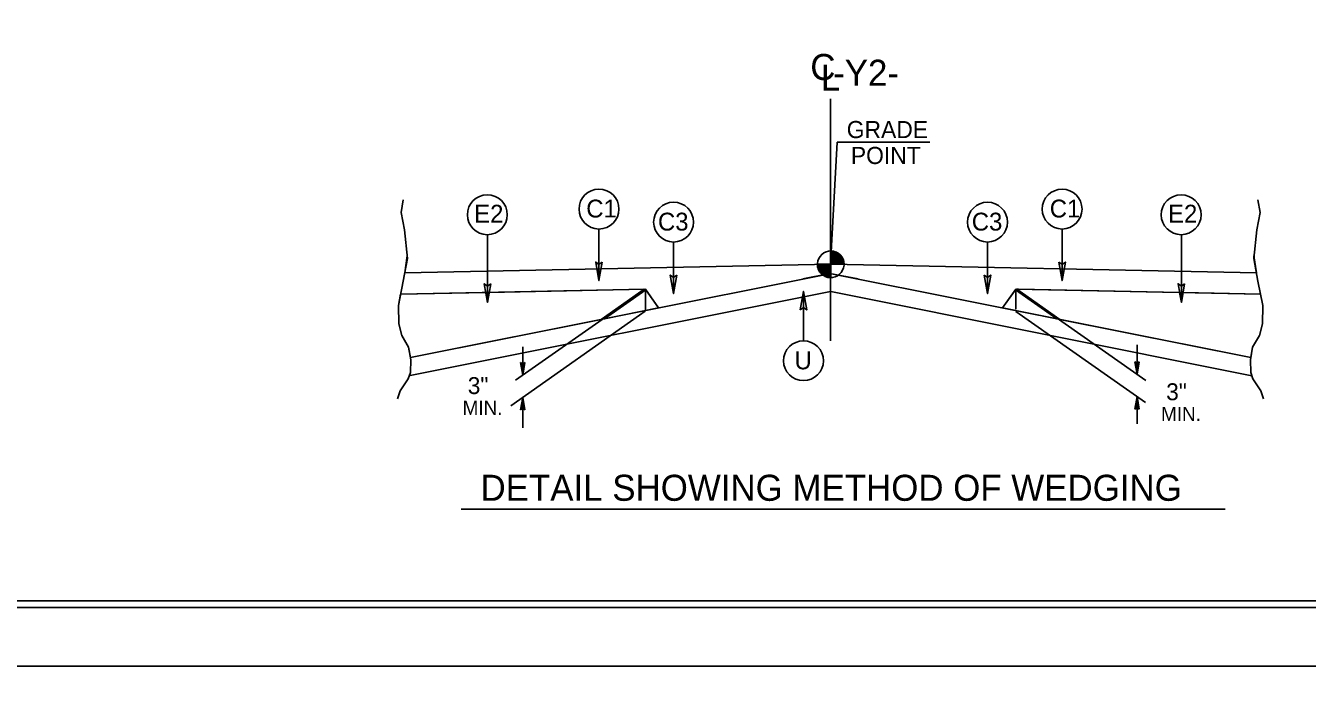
# Model space of a CAD drawing. Extents: x 1901718 to 1902220, y 193828 to 194187.
# Drawn here: x 1902024.12 to 1902073.27, y 194046.89 to 194072.58 of the extents above; entities that cross this region are included whole.
import ezdxf

# ---------------------------------------------------------------- set-up
doc = ezdxf.new("R2010")
doc.units = 0
for name, color, linetype in [('Old_Level_1', 7, 'Continuous'), ('Old_Level_11', 7, 'Continuous'), ('Old_Level_2', 7, 'Continuous'), ('Old_Level_20', 7, 'Continuous'), ('Old_Level_21', 7, 'Continuous'), ('Old_Level_3', 7, 'Continuous'), ('Sheet Border Standard 30in CELL', 7, 'Continuous'), ('Sheet Cutting Line CELL', 7, 'Continuous'), ('Sheet Plot Border Inside CELL', 7, 'Continuous'), ('Sheet Plot Border Outside CELL', 7, 'Continuous')]:
    doc.layers.add(name, color=color, linetype=linetype)

msp = doc.modelspace()

# ---------------------------------------------------------------- linework, layer by layer
at = {"layer": 'Old_Level_1'}
for p, q in [((1902054.991, 194063.427), (1902054.991, 194063.938)), ((1902054.479, 194063.427), (1902054.991, 194063.427)), ((1902054.988, 194062.916), (1902054.988, 194063.421)), ((1902054.991, 194063.427), (1902054.991, 194062.916)), ((1902055.503, 194063.427), (1902054.991, 194063.427)), ((1902054.991, 194062.916), (1902054.991, 194063.427)), ((1902047.882, 194062.471), (1902038.498, 194062.283)), ((1902054.978, 194062.385), (1902038.865, 194059.162)), ((1902047.882, 194062.471), (1902042.899, 194058.982)), ((1902048.392, 194061.754), (1902047.882, 194062.471)), ((1902047.882, 194062.471), (1902047.882, 194061.652)), ((1902054.991, 194062.385), (1902071.142, 194059.154)), ((1902061.578, 194061.755), (1902062.087, 194062.471)), ((1902062.087, 194062.471), (1902071.472, 194062.283)), ((1902062.087, 194062.471), (1902062.087, 194061.71)), ((1902062.088, 194062.471), (1902067.078, 194058.976)), ((1902047.878, 194061.627), (1902042.727, 194058.001)), ((1902047.882, 194061.653), (1902046.248, 194061.326)), ((1902061.577, 194061.755), (1902063.722, 194061.326)), ((1902062.087, 194061.611), (1902067.069, 194058.121)), ((1902046.248, 194061.326), (1902038.87, 194059.851)), ((1902043.18, 194060.262), (1902043.18, 194059.177)), ((1902066.74, 194060.342), (1902066.74, 194059.213)), ((1902043.18, 194059.177), (1902043.095, 194059.655)), ((1902043.18, 194059.593), (1902043.095, 194059.655)), ((1902043.18, 194059.177), (1902043.107, 194059.647)), ((1902043.12, 194059.637), (1902043.18, 194059.177)), ((1902043.18, 194059.177), (1902043.132, 194059.629)), ((1902043.144, 194059.62), (1902043.18, 194059.177)), ((1902043.18, 194059.177), (1902043.156, 194059.611)), ((1902043.168, 194059.602), (1902043.18, 194059.177)), ((1902043.18, 194059.177), (1902043.264, 194059.655)), ((1902043.264, 194059.655), (1902043.18, 194059.593)), ((1902043.252, 194059.647), (1902043.18, 194059.177)), ((1902043.18, 194059.177), (1902043.24, 194059.637)), ((1902043.228, 194059.629), (1902043.18, 194059.177)), ((1902043.18, 194059.177), (1902043.216, 194059.62)), ((1902043.204, 194059.611), (1902043.18, 194059.177)), ((1902043.18, 194059.177), (1902043.192, 194059.602)), ((1902043.18, 194059.593), (1902043.18, 194059.177)), ((1902066.74, 194059.213), (1902066.656, 194059.69)), ((1902066.74, 194059.629), (1902066.656, 194059.69)), ((1902066.74, 194059.213), (1902066.668, 194059.681)), ((1902066.679, 194059.673), (1902066.74, 194059.213)), ((1902066.74, 194059.213), (1902066.691, 194059.665)), ((1902066.703, 194059.655), (1902066.74, 194059.213)), ((1902066.74, 194059.213), (1902066.715, 194059.647)), ((1902066.727, 194059.637), (1902066.74, 194059.213)), ((1902066.74, 194059.213), (1902066.824, 194059.69)), ((1902066.824, 194059.69), (1902066.74, 194059.629)), ((1902066.811, 194059.681), (1902066.74, 194059.213)), ((1902066.74, 194059.213), (1902066.799, 194059.673)), ((1902066.787, 194059.665), (1902066.74, 194059.213)), ((1902066.74, 194059.213), (1902066.775, 194059.655)), ((1902066.764, 194059.647), (1902066.74, 194059.213)), ((1902066.74, 194059.213), (1902066.752, 194059.637)), ((1902066.74, 194059.629), (1902066.74, 194059.213)), ((1902043.18, 194058.319), (1902043.095, 194057.842)), ((1902043.108, 194057.851), (1902043.18, 194058.319)), ((1902043.18, 194058.319), (1902043.12, 194057.86)), ((1902043.132, 194057.868), (1902043.18, 194058.319)), ((1902043.18, 194058.319), (1902043.144, 194057.877)), ((1902043.156, 194057.886), (1902043.18, 194058.319)), ((1902043.18, 194058.319), (1902043.168, 194057.894)), ((1902043.18, 194058.319), (1902043.18, 194057.159)), ((1902043.18, 194058.319), (1902043.264, 194057.842)), ((1902043.18, 194057.904), (1902043.18, 194058.319)), ((1902043.192, 194057.894), (1902043.18, 194058.319)), ((1902043.18, 194058.319), (1902043.204, 194057.886)), ((1902043.216, 194057.877), (1902043.18, 194058.319)), ((1902043.18, 194058.319), (1902043.228, 194057.868)), ((1902043.24, 194057.86), (1902043.18, 194058.319)), ((1902043.18, 194058.319), (1902043.252, 194057.851)), ((1902066.74, 194058.352), (1902066.656, 194057.875)), ((1902066.656, 194057.875), (1902066.74, 194057.938)), ((1902066.668, 194057.884), (1902066.74, 194058.352)), ((1902066.74, 194058.352), (1902066.679, 194057.893)), ((1902066.691, 194057.902), (1902066.74, 194058.352)), ((1902066.74, 194058.352), (1902066.703, 194057.911)), ((1902066.715, 194057.92), (1902066.74, 194058.352)), ((1902066.74, 194058.352), (1902066.727, 194057.928)), ((1902066.74, 194058.352), (1902066.74, 194057.305)), ((1902066.74, 194058.352), (1902066.824, 194057.875)), ((1902066.74, 194057.938), (1902066.74, 194058.352)), ((1902066.752, 194057.928), (1902066.74, 194058.352)), ((1902066.74, 194058.352), (1902066.764, 194057.92)), ((1902066.775, 194057.911), (1902066.74, 194058.352)), ((1902066.74, 194058.352), (1902066.787, 194057.902)), ((1902066.799, 194057.893), (1902066.74, 194058.352)), ((1902066.74, 194058.352), (1902066.811, 194057.884)), ((1902066.74, 194057.938), (1902066.824, 194057.875)), ((1902043.095, 194057.842), (1902043.18, 194057.904)), ((1902043.18, 194057.904), (1902043.264, 194057.842))]:
    msp.add_line(p, q, dxfattribs=at)
for points in [[(1902038.598, 194065.896), (1902038.511, 194065.42), (1902038.641, 194064.744), (1902038.756, 194063.649), (1902038.598, 194062.785), (1902038.411, 194061.849), (1902038.425, 194061.143), (1902038.54, 194060.697), (1902038.8, 194060.25), (1902038.886, 194059.761), (1902038.872, 194059.271), (1902038.785, 194059.04), (1902038.483, 194058.579), (1902038.382, 194058.262)], [(1902071.371, 194065.896), (1902071.458, 194065.42), (1902071.328, 194064.744), (1902071.213, 194063.649), (1902071.371, 194062.785), (1902071.559, 194061.849), (1902071.544, 194061.143), (1902071.429, 194060.697), (1902071.17, 194060.25), (1902071.084, 194059.761), (1902071.098, 194059.271), (1902071.184, 194059.04), (1902071.486, 194058.579), (1902071.587, 194058.262)], [(1902054.996, 194063.938), (1902054.996, 194063.938), (1902054.996, 194063.427)], [(1902055.006, 194063.938), (1902055.006, 194063.427)], [(1902055.017, 194063.938), (1902055.017, 194063.427)], [(1902055.027, 194063.937), (1902055.027, 194063.427)], [(1902055.037, 194063.937), (1902055.037, 194063.427)], [(1902055.047, 194063.935), (1902055.047, 194063.427)], [(1902055.058, 194063.935), (1902055.058, 194063.427)], [(1902055.067, 194063.933), (1902055.067, 194063.427)], [(1902055.078, 194063.931), (1902055.078, 194063.427)], [(1902055.088, 194063.929), (1902055.088, 194063.427)], [(1902055.098, 194063.928), (1902055.098, 194063.427)], [(1902055.109, 194063.925), (1902055.109, 194063.427)], [(1902055.119, 194063.922), (1902055.119, 194063.427)], [(1902055.129, 194063.919), (1902055.129, 194063.427)], [(1902055.139, 194063.916), (1902055.139, 194063.427)], [(1902055.149, 194063.913), (1902055.149, 194063.427)], [(1902055.16, 194063.91), (1902055.16, 194063.427)], [(1902055.17, 194063.906), (1902055.17, 194063.427)], [(1902055.18, 194063.902), (1902055.18, 194063.427)], [(1902055.191, 194063.898), (1902055.19, 194063.427)], [(1902055.201, 194063.893), (1902055.201, 194063.427)], [(1902055.211, 194063.889), (1902055.211, 194063.427)], [(1902055.221, 194063.884), (1902055.221, 194063.427)], [(1902055.231, 194063.878), (1902055.231, 194063.427)], [(1902055.241, 194063.872), (1902055.241, 194063.427)], [(1902055.252, 194063.866), (1902055.252, 194063.427)], [(1902055.262, 194063.86), (1902055.262, 194063.427)], [(1902055.272, 194063.855), (1902055.272, 194063.427)], [(1902055.282, 194063.847), (1902055.282, 194063.427)], [(1902055.292, 194063.84), (1902055.292, 194063.427)], [(1902055.303, 194063.832), (1902055.303, 194063.427)], [(1902054.482, 194063.427), (1902054.482, 194063.371)], [(1902054.493, 194063.427), (1902054.493, 194063.311)], [(1902054.503, 194063.427), (1902054.503, 194063.274)], [(1902054.514, 194063.427), (1902054.514, 194063.245)], [(1902054.523, 194063.427), (1902054.523, 194063.219)], [(1902054.533, 194063.427), (1902054.533, 194063.198)], [(1902054.543, 194063.427), (1902054.543, 194063.179)], [(1902054.554, 194063.427), (1902054.554, 194063.161)], [(1902054.564, 194063.427), (1902054.564, 194063.145)], [(1902054.575, 194063.427), (1902054.575, 194063.129)], [(1902054.585, 194063.427), (1902054.585, 194063.116)], [(1902054.595, 194063.427), (1902054.595, 194063.103)], [(1902054.605, 194063.427), (1902054.605, 194063.091)], [(1902054.615, 194063.427), (1902054.615, 194063.079)], [(1902054.626, 194063.427), (1902054.626, 194063.069)], [(1902054.636, 194063.427), (1902054.636, 194063.06)], [(1902054.647, 194063.427), (1902054.647, 194063.049)], [(1902054.657, 194063.427), (1902054.656, 194063.04)], [(1902054.666, 194063.427), (1902054.666, 194063.031)], [(1902054.676, 194063.427), (1902054.676, 194063.024)], [(1902054.687, 194063.427), (1902054.687, 194063.016)], [(1902054.697, 194063.427), (1902054.697, 194063.009)], [(1902054.707, 194063.427), (1902054.707, 194063.001)], [(1902054.718, 194063.427), (1902054.718, 194062.994)], [(1902054.728, 194063.427), (1902054.728, 194062.988)], [(1902054.738, 194063.427), (1902054.738, 194062.982)], [(1902054.748, 194063.427), (1902054.748, 194062.977)], [(1902054.758, 194063.427), (1902054.758, 194062.971)], [(1902054.769, 194063.427), (1902054.769, 194062.966)], [(1902054.779, 194063.427), (1902054.779, 194062.961)], [(1902054.79, 194063.427), (1902054.79, 194062.956)], [(1902054.8, 194063.427), (1902054.799, 194062.953)], [(1902054.809, 194063.427), (1902054.809, 194062.949)], [(1902054.82, 194063.427), (1902054.82, 194062.944)], [(1902054.83, 194063.427), (1902054.83, 194062.941)], [(1902054.84, 194063.427), (1902054.84, 194062.938)], [(1902054.851, 194063.427), (1902054.851, 194062.935)], [(1902054.861, 194063.427), (1902054.861, 194062.933)], [(1902054.872, 194063.427), (1902054.871, 194062.929)], [(1902054.881, 194063.427), (1902054.881, 194062.928)], [(1902054.892, 194063.427), (1902054.891, 194062.925)], [(1902054.901, 194063.427), (1902054.901, 194062.923)], [(1902054.912, 194063.427), (1902054.912, 194062.922)], [(1902054.922, 194063.427), (1902054.922, 194062.92)], [(1902054.933, 194063.427), (1902054.933, 194062.919)], [(1902054.943, 194063.427), (1902054.942, 194062.917)], [(1902054.953, 194063.427), (1902054.953, 194062.917)], [(1902054.963, 194063.427), (1902054.963, 194062.916)], [(1902054.973, 194063.427), (1902054.973, 194062.916)], [(1902054.984, 194063.427), (1902054.984, 194062.916), (1902054.984, 194062.916)], [(1902055.313, 194063.824), (1902055.313, 194063.427)], [(1902055.324, 194063.816), (1902055.324, 194063.427)], [(1902055.334, 194063.807), (1902055.333, 194063.427)], [(1902055.344, 194063.797), (1902055.344, 194063.427)], [(1902055.354, 194063.788), (1902055.354, 194063.427)], [(1902055.364, 194063.777), (1902055.364, 194063.427)], [(1902055.375, 194063.765), (1902055.375, 194063.427)], [(1902055.385, 194063.753), (1902055.385, 194063.427)], [(1902055.396, 194063.74), (1902055.396, 194063.427)], [(1902055.406, 194063.727), (1902055.405, 194063.427)], [(1902055.416, 194063.713), (1902055.416, 194063.427)], [(1902055.425, 194063.696), (1902055.425, 194063.427)], [(1902055.435, 194063.679), (1902055.435, 194063.427)], [(1902055.446, 194063.661), (1902055.446, 194063.427)], [(1902055.457, 194063.639), (1902055.457, 194063.427)], [(1902055.467, 194063.615), (1902055.467, 194063.427)], [(1902055.477, 194063.586), (1902055.477, 194063.427)], [(1902055.487, 194063.552), (1902055.487, 194063.427)], [(1902055.497, 194063.499), (1902055.497, 194063.427)]]:
    msp.add_lwpolyline(points, dxfattribs=at)
for start, end in [(358.0003, 356.1713), (359.9905, 89.9905), (179.9905, 268.7186), (269.6533, 269.9905)]:
    msp.add_arc((1902054.991, 194063.427), 0.512, start, end, dxfattribs=at)
at = {"layer": 'Old_Level_11'}
for p, q in [((1902054.984, 194060.497), (1902054.984, 194069.78)), ((1902041.829, 194064.563), (1902041.829, 194061.968)), ((1902046.103, 194064.781), (1902046.103, 194062.803)), ((1902063.865, 194064.781), (1902063.865, 194062.803)), ((1902068.439, 194064.563), (1902068.439, 194061.968)), ((1902048.964, 194064.28), (1902048.964, 194062.302)), ((1902061.004, 194064.28), (1902061.004, 194062.302)), ((1902038.656, 194063.101), (1902038.749, 194063.753)), ((1902054.991, 194063.427), (1902038.656, 194063.101)), ((1902054.991, 194063.427), (1902071.314, 194063.101)), ((1902071.221, 194063.753), (1902071.314, 194063.101)), ((1902055.009, 194063.079), (1902038.87, 194059.851)), ((1902054.96, 194063.079), (1902053.925, 194062.864)), ((1902054.96, 194063.079), (1902071.099, 194059.851)), ((1902056.044, 194062.864), (1902054.96, 194063.079)), ((1902047.836, 194062.47), (1902043.085, 194062.375)), ((1902046.183, 194061.312), (1902047.836, 194062.47)), ((1902053.946, 194060.494), (1902053.946, 194062.388)), ((1902062.189, 194062.47), (1902062.133, 194062.47)), ((1902062.133, 194062.47), (1902063.783, 194061.315)), ((1902068.372, 194062.345), (1902062.189, 194062.47)), ((1902038.498, 194062.283), (1902038.411, 194061.849)), ((1902041.762, 194062.348), (1902038.498, 194062.283)), ((1902071.472, 194062.283), (1902068.503, 194062.342)), ((1902038.87, 194059.851), (1902046.183, 194061.312)), ((1902063.783, 194061.315), (1902063.783, 194061.315)), ((1902063.783, 194061.315), (1902063.783, 194061.315)), ((1902063.783, 194061.315), (1902063.783, 194061.315)), ((1902063.783, 194061.315), (1902063.783, 194061.315)), ((1902063.783, 194061.315), (1902063.783, 194061.315)), ((1902063.783, 194061.315), (1902063.783, 194061.315)), ((1902063.783, 194061.315), (1902071.099, 194059.851)), ((1902071.1, 194059.851), (1902071.17, 194060.25)), ((1902071.099, 194059.851), (1902071.1, 194059.851)), ((1902040.821, 194054.031), (1902070.117, 194054.031))]:
    msp.add_line(p, q, dxfattribs=at)
for points in [[(1902046.225, 194063.511), (1902046.103, 194062.803), (1902045.977, 194063.515), (1902046.103, 194063.425)], [(1902063.743, 194063.511), (1902063.865, 194062.803), (1902063.991, 194063.515), (1902063.865, 194063.425)], [(1902049.086, 194063.011), (1902048.964, 194062.302), (1902048.838, 194063.015), (1902048.964, 194062.924)], [(1902060.882, 194063.011), (1902061.004, 194062.302), (1902061.13, 194063.015), (1902061.004, 194062.924)], [(1902041.951, 194062.676), (1902041.829, 194061.968), (1902041.703, 194062.68), (1902041.829, 194062.59)], [(1902048.392, 194061.754), (1902047.896, 194062.45), (1902046.31, 194061.339)], [(1902053.824, 194061.679), (1902053.946, 194062.388), (1902054.072, 194061.675), (1902053.946, 194061.766)], [(1902062.072, 194062.451), (1902061.578, 194061.755), (1902063.659, 194061.339)], [(1902068.561, 194062.676), (1902068.439, 194061.968), (1902068.313, 194062.68), (1902068.439, 194062.59)]]:
    msp.add_lwpolyline(points, close=True, dxfattribs=at)
for points in [[(1902043.085, 194062.375), (1902041.895, 194062.351), (1902041.829, 194061.968), (1902041.762, 194062.348)], [(1902068.503, 194062.342), (1902068.439, 194061.968), (1902068.372, 194062.345)], [(1902071.17, 194060.25), (1902071.429, 194060.697), (1902071.544, 194061.143), (1902071.559, 194061.849), (1902071.472, 194062.283)], [(1902038.411, 194061.849), (1902038.425, 194061.143), (1902038.54, 194060.697)], [(1902038.54, 194060.697), (1902038.8, 194060.25), (1902038.87, 194059.851)]]:
    msp.add_lwpolyline(points, dxfattribs=at)
for centre in [(1902046.103, 194065.546), (1902063.865, 194065.546), (1902041.821, 194065.329), (1902048.964, 194065.046), (1902061.004, 194065.046), (1902068.431, 194065.329), (1902053.946, 194059.729)]:
    msp.add_circle(centre, 0.765, dxfattribs=at)
at = {"layer": 'Old_Level_3'}
for q in [(1902054.989, 194063.427), (1902058.796, 194068.111)]:
    msp.add_line((1902055.239, 194068.111), q, dxfattribs=at)
at = {"layer": 'Sheet Border Standard 30in CELL'}
msp.add_lwpolyline([(1902132.544, 194155.514), (1901982.544, 194155.514), (1901982.544, 194050.514), (1902132.544, 194050.514)], close=True, dxfattribs=at)
at = {"layer": 'Sheet Cutting Line CELL'}
for p, q in [((1901965.844, 194048.014), (1902134.244, 194048.014)), ((1902134.244, 194048.014), (1901965.844, 194048.014))]:
    msp.add_line(p, q, dxfattribs=at)
at = {"layer": 'Sheet Plot Border Inside CELL'}
msp.add_lwpolyline([(1902133.794, 194155.769), (1901967.144, 194155.769), (1901967.144, 194050.259), (1902133.794, 194050.259)], close=True, dxfattribs=at)
at = {"layer": 'Sheet Plot Border Outside CELL'}
for points in [[(1902134.244, 194158.014), (1901965.844, 194158.014), (1901965.844, 194048.014), (1902134.244, 194048.014)], [(1902134.244, 194048.014), (1901965.844, 194048.014), (1901965.844, 193938.014), (1902134.244, 193938.014)]]:
    msp.add_lwpolyline(points, close=True, dxfattribs=at)

# ---------------------------------------------------------------- texts
at = {"layer": 'Old_Level_11'}
for s, p in [('GRADE', (1902055.605, 194068.269)), ('POINT', (1902055.763, 194067.275))]:
    msp.add_text(s, height=0.656, dxfattribs=at).set_placement(p)
at = {"layer": 'Old_Level_2'}
msp.add_text('C', height=1, dxfattribs=at).set_placement((1902054.208, 194070.496))
for s, p in [('-Y2-', (1902055.083, 194070.276)), ('L', (1902054.61, 194070.092))]:
    msp.add_text(s, height=1, rotation=359.9469, dxfattribs=at).set_placement(p)
at = {"layer": 'Old_Level_20'}
for s, height, p in [('C1', 0.6851, (1902045.616, 194065.223)), ('C1', 0.6851, (1902063.392, 194065.223)), ('E2', 0.6851, (1902041.318, 194065.027)), ('C3', 0.6851, (1902048.366, 194064.722)), ('C3', 0.6851, (1902060.401, 194064.722)), ('E2', 0.6851, (1902067.928, 194065.027)), ('U', 0.685, (1902053.603, 194059.4)), ('3"', 0.6491, (1902041.072, 194058.45)), ('3"', 0.6491, (1902067.857, 194058.214))]:
    msp.add_text(s, height=height, dxfattribs=at).set_placement(p)
at = {"layer": 'Old_Level_21'}
for s, height, p in [('MIN.', 0.5424, (1902040.873, 194057.652)), ('MIN.', 0.5424, (1902067.658, 194057.416)), ('DETAIL SHOWING METHOD OF WEDGING', 1, (1902041.561, 194054.355))]:
    msp.add_text(s, height=height, dxfattribs=at).set_placement(p)

doc.saveas('drawing.dxf')
